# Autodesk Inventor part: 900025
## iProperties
Created: 2007-10
Part Number: 900025
Document SubType Name: Modeling
Designer: TH
Density: 1.13 g/cm^3
Mass: 11.233 g
Surface Area: 57.438 cm^2
Volume: 9.94074 cm^3
Material: Nylon Composite (Nylon, molybdenum disulphide)
Description: MOTOR SIDE COVER
Component Category: Electrical
Author: TH
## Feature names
1. TaggingFeature2
